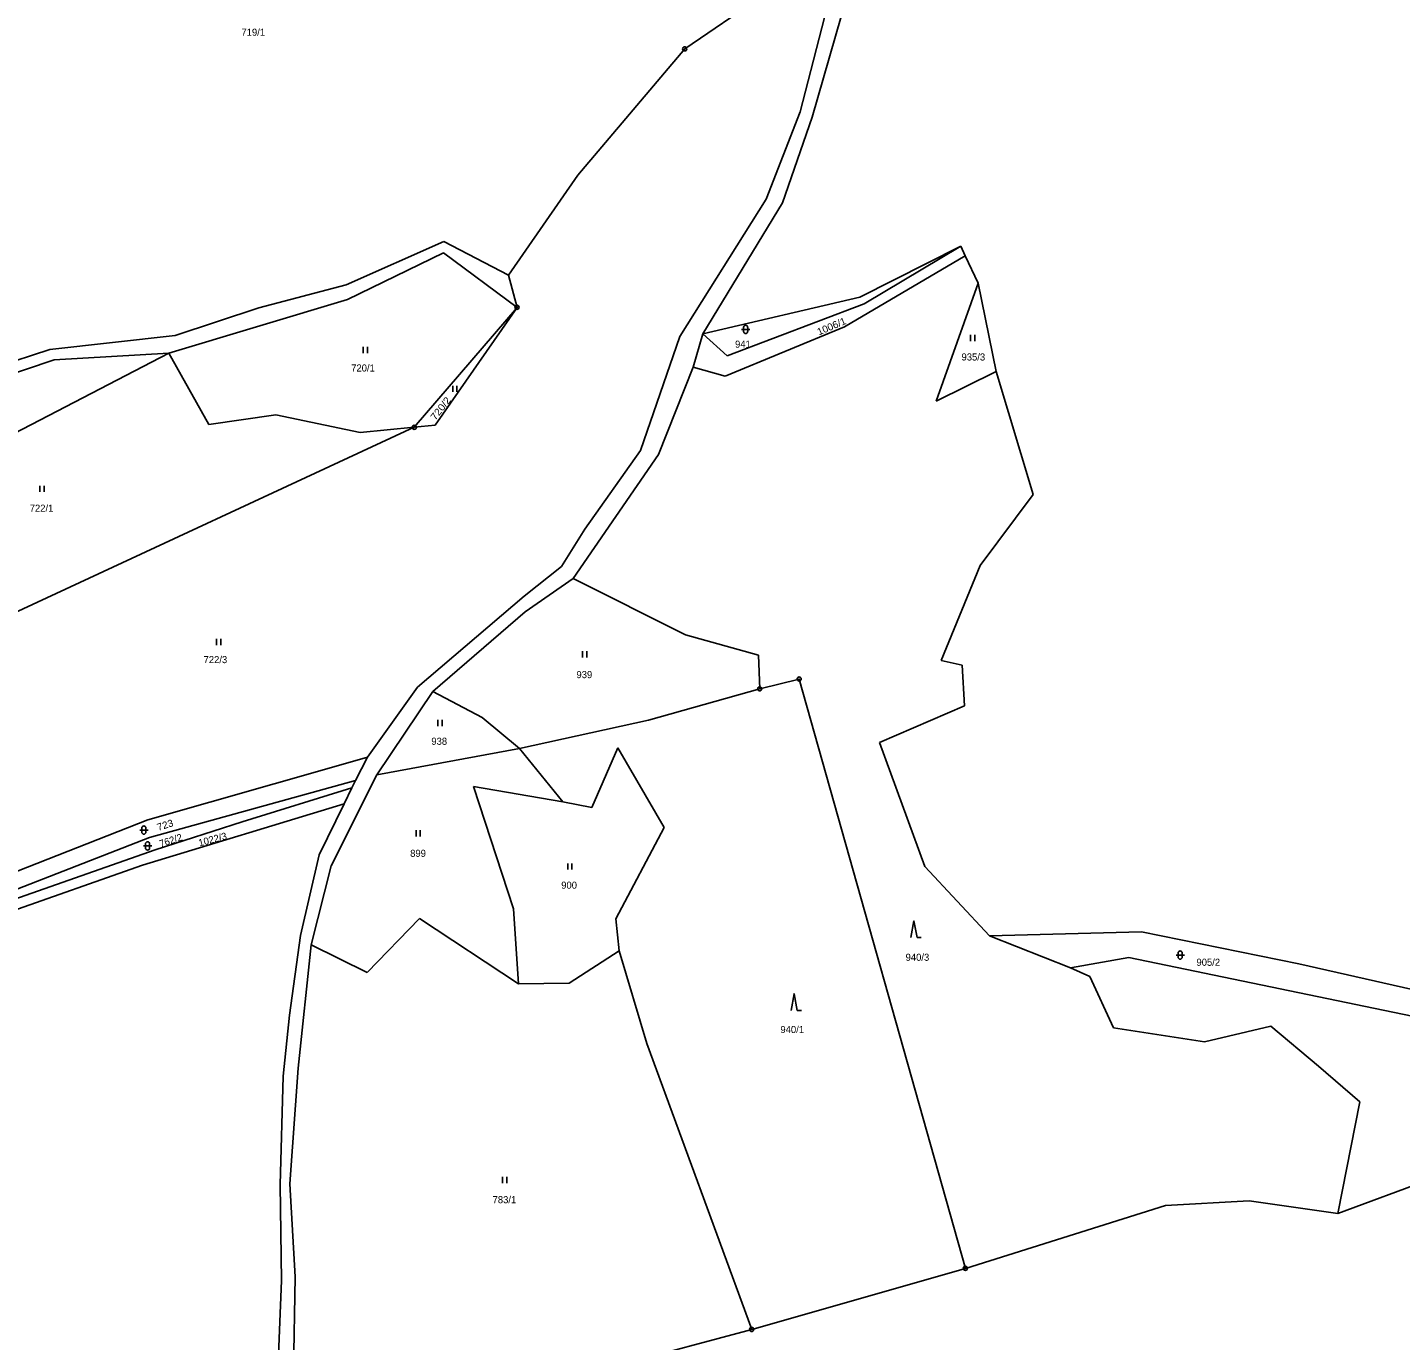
# Model space of a CAD drawing. Extents: x -754970 to -752637, y -970569 to -968179.
# Drawn here: x -754129.7 to -753799.4, y -969994.1 to -969678.2 of the extents above; entities that cross this region are included whole.
import ezdxf
from ezdxf.enums import TextEntityAlignment as Align

# ---------------------------------------------------------------- set-up
doc = ezdxf.new("R2010")
doc.units = 0
doc.header["$LTSCALE"] = 0.68
for name, color, linetype, lineweight in [('1', 7, 'Continuous', 25), ('3', 7, 'Continuous', 25), ('8', 7, 'Continuous', 25)]:
    doc.layers.add(name, color=color, linetype=linetype, lineweight=lineweight)
doc.layers.add('2', color=7, linetype='Continuous')

msp = doc.modelspace()

# ---------------------------------------------------------------- linework, layer by layer
at = {"layer": '1'}
for p, q in [((-753934.17, -969661.09), (-753943.76, -969698.49)), ((-753930.19, -969662.62), (-753940.89, -969699.78)), ((-753948.66, -969667.72), (-753971.56, -969683.36)), ((-753971.56, -969683.36), (-753997.27, -969713.72)), ((-753943.76, -969698.49), (-753951.95, -969719.53)), ((-753940.89, -969699.78), (-753948.06, -969720.41)), ((-753997.27, -969713.72), (-754013.98, -969737.79)), ((-753951.95, -969719.53), (-753972.7, -969752.54)), ((-753967.18, -969751.9), (-753948.06, -969720.41)), ((-754029.49, -969729.7), (-754052.98, -969740.12)), ((-754013.98, -969737.79), (-754029.49, -969729.7)), ((-754029.6, -969732.47), (-754052.65, -969743.67)), ((-754011.91, -969745.56), (-754029.6, -969732.47)), ((-753904.08, -969733.14), (-753933.15, -969750.27)), ((-753905.1, -969730.86), (-753929.45, -969743.1)), ((-753905.1, -969730.86), (-753928.43, -969744.67)), ((-753905.1, -969730.86), (-753904.08, -969733.14)), ((-753904.08, -969733.14), (-753900.98, -969739.76)), ((-754052.98, -969740.12), (-754074.04, -969745.67)), ((-754013.98, -969737.79), (-754011.91, -969745.56)), ((-753900.98, -969739.76), (-753911.09, -969768.13)), ((-753900.98, -969739.76), (-753896.65, -969761)), ((-753967.18, -969751.9), (-753929.45, -969743.1)), ((-754052.65, -969743.67), (-754095.67, -969756.55)), ((-754074.04, -969745.67), (-754094.16, -969752.34)), ((-754036.61, -969774.4), (-754011.91, -969745.56)), ((-754011.91, -969745.56), (-754031.63, -969773.93)), ((-753928.43, -969744.67), (-753961.35, -969757.23)), ((-754094.16, -969752.34), (-754124.26, -969755.69)), ((-753972.7, -969752.54), (-753982.19, -969779.98)), ((-753969.5, -969759.91), (-753967.18, -969751.9)), ((-753967.18, -969751.9), (-753961.35, -969757.23)), ((-753961.86, -969762.13), (-753933.15, -969750.27)), ((-754124.26, -969755.69), (-754149.61, -969764)), ((-754139.48, -969779.31), (-754095.67, -969756.55)), ((-754123.29, -969758.17), (-754095.67, -969756.55)), ((-754095.67, -969756.55), (-754086.01, -969773.72)), ((-754145.62, -969765.72), (-754123.29, -969758.17)), ((-753977.9, -969780.95), (-753969.5, -969759.91)), ((-753969.5, -969759.91), (-753961.86, -969762.13)), ((-753911.09, -969768.13), (-753896.65, -969761)), ((-753896.65, -969761), (-753887.76, -969790.56)), ((-754086.01, -969773.72), (-754069.94, -969771.39)), ((-754069.94, -969771.39), (-754049.63, -969775.63)), ((-754132.99, -969819.13), (-754036.61, -969774.4)), ((-754049.63, -969775.63), (-754036.61, -969774.4)), ((-754031.63, -969773.93), (-754036.61, -969774.4)), ((-753998.39, -969810.82), (-753977.9, -969780.95)), ((-753982.19, -969779.98), (-753995.56, -969798.91)), ((-753887.76, -969790.56), (-753900.52, -969807.63)), ((-754001.21, -969807.89), (-753995.56, -969798.91)), ((-754010.19, -969815.01), (-754001.21, -969807.89)), ((-753909.89, -969830.52), (-753900.52, -969807.63)), ((-753998.39, -969810.82), (-754009.97, -969818.79)), ((-754035.86, -969836.89), (-754010.19, -969815.01)), ((-754009.97, -969818.79), (-754032.19, -969837.97)), ((-753953.78, -969829.2), (-753953.53, -969837.32)), ((-753904.83, -969831.64), (-753909.89, -969830.52)), ((-753904.27, -969841.4), (-753904.83, -969831.64)), ((-753953.53, -969837.32), (-753944.03, -969834.97)), ((-753944.03, -969834.97), (-753904.04, -969976.75)), ((-754047.91, -969853.8), (-754035.86, -969836.89)), ((-754045.65, -969858.04), (-754032.19, -969837.97)), ((-754020.3, -969844.26), (-754032.19, -969837.97)), ((-753980.31, -969844.86), (-753953.53, -969837.32)), ((-753924.71, -969850.22), (-753904.27, -969841.4)), ((-754011.27, -969851.65), (-754020.3, -969844.26)), ((-753980.31, -969844.86), (-754011.27, -969851.65)), ((-754011.27, -969851.65), (-754045.65, -969858.04)), ((-754000.88, -969864.49), (-754011.27, -969851.65)), ((-753987.62, -969851.51), (-753993.91, -969865.86)), ((-753976.54, -969870.66), (-753987.62, -969851.51)), ((-753913.83, -969880.04), (-753924.71, -969850.22)), ((-754055.43, -969855.92), (-754100.7, -969868.84)), ((-754045.65, -969858.04), (-754056.59, -969879.93)), ((-754050.78, -969859.41), (-754100.35, -969873.08)), ((-754051.63, -969861.16), (-754078.05, -969869.32)), ((-754053.51, -969865.01), (-754051.63, -969861.16)), ((-754051.63, -969861.16), (-754050.78, -969859.41)), ((-754022.35, -969860.81), (-754012.78, -969890.22)), ((-754000.88, -969864.49), (-754022.35, -969860.81)), ((-754053.51, -969865.01), (-754101.99, -969879.78)), ((-754059.53, -969877.26), (-754053.51, -969865.01)), ((-753993.91, -969865.86), (-754000.88, -969864.49)), ((-754100.7, -969868.84), (-754134.54, -969882.17)), ((-754098.98, -969876.02), (-754078.05, -969869.32)), ((-753988.16, -969892.68), (-753976.54, -969870.66)), ((-754133.86, -969886.14), (-754100.35, -969873.08)), ((-754134.54, -969888.6), (-754098.98, -969876.02)), ((-754063.97, -969896.68), (-754059.53, -969877.26)), ((-754101.99, -969879.78), (-754134.81, -969891.27)), ((-754056.59, -969879.93), (-754061.44, -969898.94)), ((-753898.26, -969896.75), (-753913.83, -969880.04)), ((-754012.78, -969890.22), (-754011.55, -969908.27)), ((-754047.92, -969905.53), (-754035.34, -969892.54)), ((-754035.34, -969892.54), (-754011.55, -969908.27)), ((-754063.97, -969896.68), (-754066.63, -969915.83)), ((-753898.26, -969896.75), (-753861.69, -969895.81)), ((-753878.76, -969904.44), (-753898.26, -969896.75)), ((-753823.81, -969903.5), (-753861.69, -969895.81)), ((-754061.44, -969898.94), (-754064.58, -969928.62)), ((-754061.44, -969898.94), (-754047.92, -969905.53)), ((-753980.65, -969922.63), (-753987.34, -969900.34)), ((-753878.76, -969904.44), (-753864.69, -969902)), ((-753864.69, -969902), (-753783.11, -969918.89)), ((-753874.07, -969906.5), (-753878.76, -969904.44)), ((-753823.81, -969903.5), (-753789.11, -969911.38)), ((-754011.55, -969908.27), (-753999.38, -969908.14)), ((-753874.07, -969906.5), (-753868.44, -969918.89)), ((-754068.14, -969930.53), (-754066.63, -969915.83)), ((-753830.56, -969918.51), (-753846.5, -969922.26)), ((-753819.12, -969928.08), (-753830.56, -969918.51)), ((-753846.5, -969922.26), (-753868.44, -969918.89)), ((-753980.65, -969922.63), (-753955.45, -969991.45)), ((-753809.18, -969936.71), (-753819.12, -969928.08)), ((-754068.88, -969956.66), (-754068.14, -969930.53)), ((-754064.58, -969928.62), (-754066.55, -969956.45)), ((-753814.43, -969963.54), (-753809.18, -969936.71)), ((-753814.43, -969963.54), (-753788.17, -969953.78)), ((-754068.6, -969979.64), (-754068.88, -969956.66)), ((-754066.55, -969956.45), (-754065.25, -969978.75)), ((-753855.88, -969961.66), (-753835.81, -969960.53)), ((-753835.81, -969960.53), (-753814.43, -969963.54)), ((-753904.04, -969976.75), (-753855.88, -969961.66)), ((-753955.45, -969991.45), (-753904.04, -969976.75)), ((-754070.1, -970019.91), (-754068.6, -969979.64)), ((-754065.25, -969978.75), (-754065.92, -970016.48)), ((-753955.45, -969991.45), (-753986.6, -969999.8))]:
    msp.add_line(p, q, dxfattribs=at)
for points in [[(-753998.39, -969810.82), (-753971.41, -969824.32), (-753953.78, -969829.2)], [(-754050.78, -969859.41), (-754047.91, -969853.8), (-754055.43, -969855.92)], [(-753999.38, -969908.14), (-753987.34, -969900.34), (-753988.16, -969892.68)]]:
    msp.add_lwpolyline(points, dxfattribs=at)
at = {"layer": '3'}
for p, q in [((-753957.921, -969750.861), (-753955.919, -969750.861)), ((-753957.421, -969750.361), (-753957.421, -969751.362)), ((-753956.419, -969751.362), (-753956.419, -969750.361)), ((-753902.791, -969753.67), (-753902.791, -969752.17)), ((-753901.79, -969753.67), (-753901.79, -969752.17)), ((-754048.911, -969756.54), (-754048.911, -969755.04)), ((-754047.91, -969756.54), (-754047.91, -969755.04)), ((-754027.351, -969765.91), (-754027.351, -969764.41)), ((-754026.35, -969765.91), (-754026.35, -969764.41)), ((-754126.671, -969789.95), (-754126.671, -969788.45)), ((-754125.67, -969789.95), (-754125.67, -969788.45)), ((-754084.191, -969826.78), (-754084.191, -969825.28)), ((-754083.19, -969826.78), (-754083.19, -969825.28)), ((-753996.131, -969829.79), (-753996.131, -969828.29)), ((-753995.13, -969829.79), (-753995.13, -969828.29)), ((-754030.951, -969846.28), (-754030.951, -969844.78)), ((-754029.95, -969846.28), (-754029.95, -969844.78)), ((-754102.681, -969871.311), (-754100.679, -969871.311)), ((-754102.181, -969870.811), (-754102.181, -969871.812)), ((-754101.179, -969871.812), (-754101.179, -969870.811)), ((-754036.191, -969872.85), (-754036.191, -969871.35)), ((-754035.19, -969872.85), (-754035.19, -969871.35)), ((-754101.791, -969875.131), (-754099.789, -969875.131)), ((-754101.291, -969874.631), (-754101.291, -969875.632)), ((-754100.289, -969875.632), (-754100.289, -969874.631)), ((-753999.701, -969880.82), (-753999.701, -969879.32)), ((-753998.7, -969880.82), (-753998.7, -969879.32)), ((-753915.66, -969897.14), (-753914.664, -969897.14)), ((-753853.371, -969901.381), (-753851.369, -969901.381)), ((-753852.871, -969900.881), (-753852.871, -969901.882)), ((-753851.869, -969901.882), (-753851.869, -969900.881)), ((-753944.49, -969914.7), (-753943.494, -969914.7)), ((-754015.381, -969956.22), (-754015.381, -969954.72)), ((-754014.38, -969956.22), (-754014.38, -969954.72))]:
    msp.add_line(p, q, dxfattribs=at)
for points in [[(-753915.66, -969897.14), (-753916.41, -969893.14), (-753917.16, -969897.14)], [(-753944.49, -969914.7), (-753945.24, -969910.7), (-753945.99, -969914.7)]]:
    msp.add_lwpolyline(points, dxfattribs=at)
for centre, start, end in [((-753956.92, -969750.3609), 0, 180), ((-753956.92, -969751.3609), 180, 359.98789), ((-754101.68, -969870.8109), 0, 180), ((-754101.68, -969871.8109), 180, 359.98789), ((-754100.79, -969874.6309), 0, 180), ((-754100.79, -969875.6309), 180, 359.98789), ((-753852.37, -969900.8809), 0, 180), ((-753852.37, -969901.8809), 180, 359.98789)]:
    msp.add_arc(centre, 0.5, start, end, dxfattribs=at)
at = {"layer": '8'}
for centre, radius in [((-753971.56, -969683.3599), 0.5), ((-753971.56, -969683.3599), 0.0303), ((-754011.91, -969745.5599), 0.5), ((-754011.91, -969745.5599), 0.0303), ((-754036.61, -969774.3999), 0.5), ((-754036.61, -969774.3999), 0.0303), ((-753944.03, -969834.9699), 0.5), ((-753944.03, -969834.9699), 0.0303), ((-753953.53, -969837.3199), 0.5), ((-753953.53, -969837.3199), 0.0303), ((-753904.04, -969976.7499), 0.5), ((-753904.04, -969976.7499), 0.0303), ((-753955.45, -969991.4499), 0.5), ((-753955.45, -969991.4499), 0.0303)]:
    msp.add_circle(centre, radius, dxfattribs=at)

# ---------------------------------------------------------------- texts
at = {"layer": '2'}
for s, p in [('719/1', (-754075.36, -969680.205)), ('941', (-753957.559, -969755.245)), ('935/3', (-753902.13, -969758.335)), ('720/1', (-754048.96, -969760.985)), ('722/1', (-754126.29, -969794.705)), ('722/3', (-754084.47, -969831.145)), ('939', (-753995.709, -969834.755)), ('938', (-754030.619, -969850.785)), ('899', (-754035.719, -969877.745)), ('900', (-753999.379, -969885.415)), ('940/3', (-753915.58, -969902.755)), ('905/2', (-753845.61, -969903.955)), ('940/1', (-753945.7, -969920.135)), ('783/1', (-754014.94, -969961.075))]:
    msp.add_text(s, height=1.7, dxfattribs=at).set_placement(p, align=Align.CENTER)
for s, rotation, width, p in [('1006/1', 23, 1.05, (-753935.9141, -969750.8888)), ('720/2', 52, 1.1, (-754029.6065, -969770.3943)), ('723', 18, 1.05, (-754096.3047, -969870.9001))]:
    msp.add_text(s, height=1.7, rotation=rotation, dxfattribs=dict(at, width=width)).set_placement(p, align=Align.CENTER)
for s, rotation, p in [('762/2', 18, (-754094.9437, -969874.6)), ('1022/3', 15, (-754084.928, -969874.3599))]:
    msp.add_text(s, height=1.7, rotation=rotation, dxfattribs=at).set_placement(p, align=Align.CENTER)

doc.saveas('drawing.dxf')
